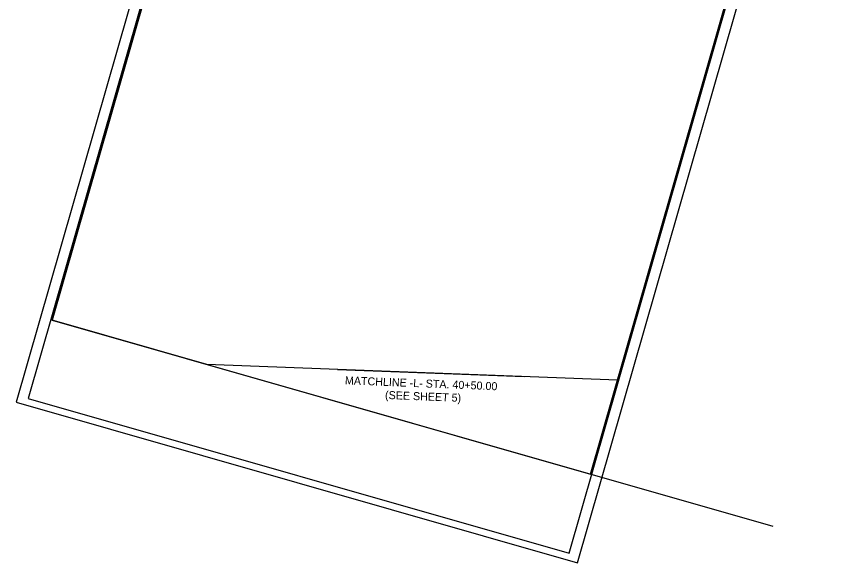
# Model space of a CAD drawing. Extents: x 2096093 to 2098911, y 683546 to 689764.
# Drawn here: x 2096990 to 2098506, y 687712 to 688738 of the extents above; entities that cross this region are included whole.
import ezdxf

# ---------------------------------------------------------------- set-up
doc = ezdxf.new("R2010")
doc.units = 0
for name, color, linetype in [('Matchline', 7, 'Continuous'), ('Matchline Text', 7, 'Continuous'), ('Prop DSN Text', 7, 'Continuous'), ('Scratch_Level_5', 7, 'Continuous'), ('Sheet Plan CELL', 7, 'Continuous'), ('Sheet Plot Border Inside CELL', 7, 'Continuous'), ('Sheet Plot Border Outside CELL', 7, 'Continuous')]:
    doc.layers.add(name, color=color, linetype=linetype)

msp = doc.modelspace()

# ---------------------------------------------------------------- linework, layer by layer
at = {"layer": 'Matchline'}
msp.add_line((2097592.7, 688074.6), (2097942.4, 688061.2), dxfattribs=at)
at = {"layer": 'Prop DSN Text'}
msp.add_line((2097057.8, 688167), (2098408.7, 687780.3), dxfattribs=at)
at = {"layer": 'Scratch_Level_5'}
msp.add_lwpolyline([(2098117.8, 688054.5), (2097347.7, 688084), (2097057.8, 688167), (2097419.2, 689429.5), (2097641.1, 689366), (2097692.5, 689545.5), (2098409.8, 689340.2), (2098316.6, 689014.7), (2098387, 688994.6)], close=True, dxfattribs=at)
at = {"layer": 'Sheet Plan CELL'}
msp.add_lwpolyline([(2097470.8, 689609.1), (2097057.9, 688167.1), (2098067.3, 687878), (2098480.2, 689320)], close=True, dxfattribs=at)
at = {"layer": 'Sheet Plot Border Inside CELL'}
msp.add_lwpolyline([(2098027.3, 687729.7), (2098485.9, 689331.3), (2097471.7, 689621.8), (2097013, 688020.1)], close=True, dxfattribs=at)
msp.add_lwpolyline([(2098027.3, 687729.7), (2098485.9, 689331.3), (2097471.7, 689621.8), (2097013, 688020.1)], close=True, dxfattribs=at)
at = {"layer": 'Sheet Plot Border Outside CELL'}
msp.add_lwpolyline([(2098042.9, 687711.7), (2098506.4, 689330.1), (2097453.7, 689631.6), (2096990.2, 688013.2)], close=True, dxfattribs=at)
msp.add_lwpolyline([(2098042.9, 687711.7), (2098506.4, 689330.1), (2097453.7, 689631.6), (2096990.2, 688013.2)], close=True, dxfattribs=at)

# ---------------------------------------------------------------- texts
at = {"layer": 'Matchline Text'}
for s, p in [('MATCHLINE -L- STA. 40+50.00', (2097606.4, 688046.8)), ('(SEE SHEET 5)', (2097681.6, 688019.4))]:
    msp.add_text(s, height=15, rotation=357.7373, dxfattribs=at).set_placement(p)

doc.saveas('drawing.dxf')
